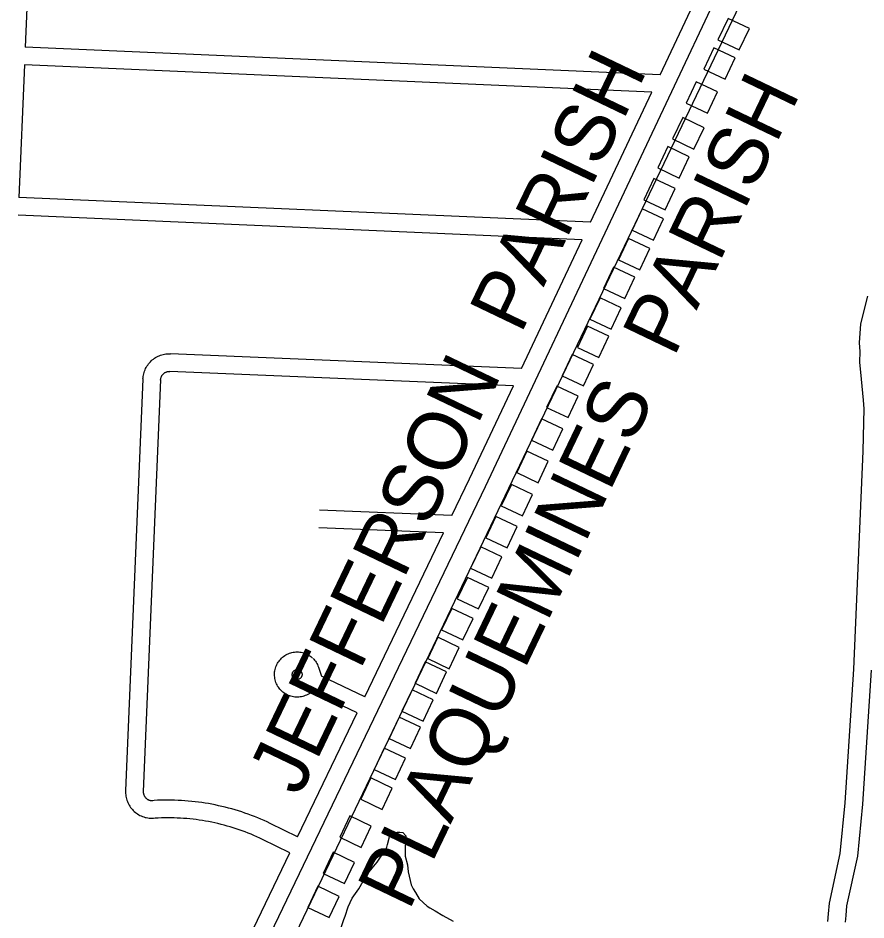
# Model space of a CAD drawing. Extents: x 3683402 to 3721514, y 487807 to 513565.
# Drawn here: x 3699136 to 3700574, y 507452 to 508980 of the extents above; entities that cross this region are included whole.
import ezdxf

# ---------------------------------------------------------------- set-up
doc = ezdxf.new("R2010")
doc.units = 0
for name, color, linetype in [('V-BLDG-OTLN', 7, 'Continuous'), ('V-ROAD-CNTR', 7, 'Continuous'), ('V-SITE-VEGE', 7, 'Continuous'), ('V-TOPO-BNDY', 7, 'Continuous'), ('V-TOPO-GNAM-IDEN', 7, 'Continuous')]:
    doc.layers.add(name, color=color, linetype=linetype)

msp = doc.modelspace()

# ---------------------------------------------------------------- linework, layer by layer
at = {"layer": 'V-BLDG-OTLN'}
for points in [[(3700339.8, 508979.8), (3700322.7, 508943.7), (3700358.8, 508926.6), (3700375.9, 508962.7)], [(3700315.7, 508929.9), (3700298.6, 508893.8), (3700334.8, 508876.7), (3700351.9, 508912.8)], [(3700285.6, 508872.4), (3700268.5, 508836.2), (3700304.7, 508819.1), (3700321.8, 508855.3)], [(3700262.9, 508811.5), (3700245.8, 508775.4), (3700282, 508758.3), (3700299.1, 508794.5)], [(3700237.9, 508762.4), (3700220.8, 508726.2), (3700257, 508709.1), (3700274.1, 508745.3)], [(3700214, 508708.3), (3700196.9, 508672.1), (3700233.1, 508655), (3700250.2, 508691.2)], [(3700194.1, 508657), (3700177, 508620.9), (3700213.2, 508603.8), (3700230.3, 508639.9)], [(3700171, 508606.6), (3700153.9, 508570.5), (3700190.1, 508553.4), (3700207.1, 508589.6)], [(3700145.8, 508558.3), (3700128.7, 508522.1), (3700164.9, 508505), (3700182, 508541.2)], [(3700122.7, 508506.2), (3700105.6, 508470), (3700141.7, 508452.9), (3700158.8, 508489.1)], [(3700101.5, 508458.2), (3700084.4, 508422), (3700120.5, 508404.9), (3700137.6, 508441.1)], [(3700075.5, 508410), (3700058.4, 508373.8), (3700094.6, 508356.7), (3700111.7, 508392.9)], [(3700049.3, 508356.3), (3700032.2, 508320.1), (3700068.4, 508303), (3700085.5, 508339.2)], [(3700023.7, 508301.2), (3700006.6, 508265.1), (3700042.8, 508248), (3700059.9, 508284.1)], [(3699998.8, 508246.1), (3699981.7, 508209.9), (3700017.8, 508192.8), (3700034.9, 508229)], [(3699972.3, 508189.7), (3699955.2, 508153.6), (3699991.3, 508136.5), (3700008.4, 508172.7)], [(3699945.9, 508135.7), (3699928.8, 508099.5), (3699965, 508082.4), (3699982.1, 508118.6)], [(3699920.3, 508084.3), (3699903.2, 508048.1), (3699939.3, 508031), (3699956.4, 508067.2)], [(3699897.7, 508032.2), (3699880.6, 507996), (3699916.8, 507978.9), (3699933.9, 508015.1)], [(3699871.2, 507979.6), (3699854.1, 507943.5), (3699890.3, 507926.4), (3699907.4, 507962.5)], [(3699847.6, 507930.7), (3699830.6, 507894.5), (3699866.7, 507877.4), (3699883.8, 507913.6)], [(3699826.4, 507889), (3699809.3, 507852.8), (3699845.5, 507835.7), (3699862.6, 507871.9)], [(3699803.9, 507841.8), (3699786.8, 507805.6), (3699822.9, 507788.5), (3699840, 507824.7)], [(3699782.3, 507795.3), (3699765.2, 507759.2), (3699801.4, 507742.1), (3699818.5, 507778.2)], [(3699756.7, 507742.7), (3699739.6, 507706.5), (3699775.8, 507689.4), (3699792.9, 507725.6)], [(3699734.2, 507692.3), (3699717.1, 507656.1), (3699753.2, 507639), (3699770.3, 507675.2)], [(3699698.5, 507627.8), (3699681.4, 507591.7), (3699717.6, 507574.6), (3699734.7, 507610.7)], [(3699670.4, 507566.3), (3699653.3, 507530.2), (3699689.5, 507513.1), (3699706.6, 507549.2)], [(3699644.3, 507508.7), (3699627.2, 507472.6), (3699663.3, 507455.5), (3699680.4, 507491.6)]]:
    msp.add_lwpolyline(points, close=True, dxfattribs=at)
at = {"layer": 'V-ROAD-CNTR'}
for points in [[(3699500.7, 507296.2), (3699928.4, 508186.2), (3700399.8, 509185.7), (3700409.1, 509207.3), (3700415, 509225.2), (3700418, 509244.9), (3700421.8, 509363)], [(3699157.5, 509155.7), (3699147.9, 508931.1)], [(3700224.4, 508884.1), (3700328.1, 509103.9)], [(3700224.4, 508884.1), (3699147.9, 508931.1)], [(3699146.6, 508901.1), (3699137, 508676.3)], [(3700210.5, 508854.7), (3699146.6, 508901.1)], [(3700106.5, 508634.1), (3700210.5, 508854.7)], [(3700106.5, 508634.1), (3699137, 508676.3)], [(3700092.6, 508604.7), (3699135.7, 508646.4)], [(3699989.5, 508386.1), (3700092.6, 508604.7)], [(3700509.2, 507449.2), (3700510.1, 507461.7), (3700511.6, 507480.1), (3700530.1, 507564.2), (3700538.5, 507650.3), (3700553.1, 507876.6), (3700568.8, 508246.1), (3700570.2, 508294.9), (3700570.5, 508318), (3700569.4, 508332.6), (3700566.1, 508368.3), (3700563.5, 508397.1), (3700563.7, 508415.2), (3700562.8, 508429.8), (3700565, 508461.9), (3700577, 508509)], [(3699347.6, 508368.7), (3699347.7, 508370.7), (3699348, 508373), (3699348.4, 508375.3), (3699348.9, 508377.5), (3699349.5, 508379.8), (3699350.3, 508382), (3699351.1, 508384.1), (3699352.1, 508386.2), (3699353.2, 508388.3), (3699354.3, 508390.3), (3699355.6, 508392.2), (3699357, 508394.1), (3699358.5, 508395.9), (3699360.1, 508397.6), (3699361.7, 508399.3), (3699363.4, 508400.8), (3699365.3, 508402.3), (3699367.1, 508403.6), (3699369.1, 508404.9), (3699371.1, 508406), (3699373.2, 508407.1), (3699375.3, 508408), (3699377.5, 508408.9), (3699379.7, 508409.6), (3699381.9, 508410.2), (3699384.2, 508410.7), (3699386.5, 508411), (3699388.8, 508411.3), (3699391.1, 508411.4), (3699393.3, 508411.4), (3699394.3, 508411.4)], [(3699989.5, 508386.1), (3699394.4, 508411.4)], [(3699377.5, 508366.7), (3699377.6, 508367.9), (3699377.7, 508368.6), (3699377.8, 508369.4), (3699378, 508370.1), (3699378.2, 508370.9), (3699378.4, 508371.6), (3699378.7, 508372.3), (3699379, 508373), (3699379.4, 508373.7), (3699379.8, 508374.4), (3699380.2, 508375), (3699380.7, 508375.7), (3699381.2, 508376.3), (3699381.7, 508376.8), (3699382.2, 508377.4), (3699382.8, 508377.9), (3699383.4, 508378.4), (3699384.1, 508378.8), (3699384.7, 508379.3), (3699385.4, 508379.6), (3699386.1, 508380), (3699386.8, 508380.3), (3699387.5, 508380.6), (3699388.2, 508380.8), (3699389, 508381), (3699389.7, 508381.2), (3699390.5, 508381.3), (3699391.3, 508381.4), (3699392, 508381.4), (3699392.9, 508381.4), (3699393.3, 508381.4)], [(3699975.7, 508356.7), (3699393.2, 508381.4)], [(3699347.6, 508368.3), (3699318.1, 507670.8)], [(3699377.5, 508367.1), (3699348.1, 507669.5)], [(3699871.6, 508137.2), (3699901.3, 508199.1), (3699975.7, 508356.7)], [(3699871.6, 508137.2), (3699646.8, 508146.2)], [(3699857.4, 508107.8), (3699645.6, 508116.2)], [(3699723.7, 507829.6), (3699857.4, 508107.8)], [(3699636.1, 507838.1), (3699624.8, 507832.6), (3699622.8, 507831.8), (3699620.6, 507831), (3699618.5, 507830.4), (3699616.3, 507829.9), (3699614.1, 507829.6), (3699611.8, 507829.3), (3699609.6, 507829.2), (3699607.4, 507829.3), (3699605.1, 507829.4), (3699602.9, 507829.7), (3699600.7, 507830.1), (3699598.5, 507830.7), (3699596.4, 507831.4), (3699594.3, 507832.2), (3699592.2, 507833.1), (3699590.2, 507834.1), (3699588.3, 507835.3), (3699586.5, 507836.6), (3699584.7, 507837.9), (3699583, 507839.4), (3699581.4, 507841), (3699579.9, 507842.7), (3699578.5, 507844.4), (3699577.2, 507846.2), (3699576, 507848.1), (3699574.9, 507850.1), (3699573.9, 507852.1), (3699573.1, 507854.2), (3699572.4, 507856.3), (3699571.8, 507858.5), (3699571.3, 507860.7), (3699571, 507862.9), (3699570.8, 507865.2), (3699570.7, 507867.4), (3699570.8, 507869.6), (3699570.9, 507871.9), (3699571.3, 507874.1), (3699571.7, 507876.3), (3699572.3, 507878.5), (3699573, 507880.6), (3699573.8, 507882.7), (3699574.7, 507884.7), (3699575.8, 507886.7), (3699577, 507888.6), (3699578.3, 507890.5), (3699579.7, 507892.2), (3699581.2, 507893.9), (3699582.7, 507895.5), (3699584.4, 507897), (3699586.2, 507898.4), (3699588, 507899.6), (3699589.9, 507900.8), (3699591.9, 507901.9), (3699594, 507902.8), (3699596, 507903.7), (3699598.2, 507904.3), (3699600.3, 507904.9), (3699602.5, 507905.4), (3699604.8, 507905.7), (3699607, 507905.9), (3699609.3, 507905.9), (3699611.5, 507905.8), (3699613.7, 507905.6), (3699616, 507905.3), (3699618.1, 507904.8), (3699620.3, 507904.2), (3699622.4, 507903.5), (3699624.5, 507902.7), (3699626.5, 507901.7), (3699628.5, 507900.6), (3699630.4, 507899.4), (3699632.2, 507898.1), (3699634, 507896.7), (3699635.3, 507895.5)], [(3699636, 507894.9), (3699637.2, 507893.6), (3699638.7, 507891.9), (3699640.1, 507890.1), (3699641.3, 507888.3), (3699642.5, 507886.3), (3699643.5, 507884.4), (3699644.4, 507882.3), (3699645.3, 507880.2), (3699650.2, 507864.6)], [(3699616.8, 507864.4), (3699616.4, 507863.6), (3699616.1, 507863.1), (3699615.8, 507862.7), (3699615.5, 507862.3), (3699615.2, 507862), (3699614.9, 507861.6), (3699614.5, 507861.3), (3699614.1, 507861), (3699613.8, 507860.7), (3699613.3, 507860.4), (3699612.9, 507860.2), (3699612.5, 507860), (3699612, 507859.8), (3699611.6, 507859.6), (3699611.1, 507859.5), (3699610.6, 507859.4), (3699610.1, 507859.3), (3699609.7, 507859.3), (3699609.2, 507859.2), (3699608.7, 507859.2), (3699608.2, 507859.3), (3699607.7, 507859.3), (3699607.2, 507859.4), (3699606.8, 507859.6), (3699606.3, 507859.7), (3699605.8, 507859.9), (3699605.4, 507860.1), (3699605, 507860.3), (3699604.5, 507860.6), (3699604.1, 507860.8), (3699603.7, 507861.1), (3699603.4, 507861.5), (3699603, 507861.8), (3699602.7, 507862.2), (3699602.4, 507862.5), (3699602.1, 507862.9), (3699601.9, 507863.3), (3699601.6, 507863.8), (3699601.4, 507864.2), (3699601.2, 507864.7), (3699601.1, 507865.1), (3699600.9, 507865.6), (3699600.8, 507866.1), (3699600.8, 507866.6), (3699600.7, 507867), (3699600.7, 507867.5), (3699600.7, 507868), (3699600.8, 507868.5), (3699600.8, 507869), (3699600.9, 507869.5), (3699601.1, 507869.9), (3699601.2, 507870.4), (3699601.4, 507870.9), (3699601.6, 507871.3), (3699601.8, 507871.7), (3699602.1, 507872.1), (3699602.4, 507872.5), (3699602.7, 507872.9), (3699603, 507873.3), (3699603.3, 507873.6), (3699603.7, 507874), (3699604.1, 507874.3), (3699604.5, 507874.5), (3699604.9, 507874.8), (3699605.3, 507875), (3699605.8, 507875.2), (3699606.2, 507875.4), (3699606.7, 507875.6), (3699607.2, 507875.7), (3699607.6, 507875.8), (3699608.1, 507875.9), (3699608.6, 507875.9), (3699609.1, 507875.9), (3699609.6, 507875.9), (3699610.1, 507875.8), (3699610.5, 507875.8), (3699611, 507875.7), (3699611.5, 507875.5), (3699612, 507875.4), (3699612.4, 507875.2), (3699612.8, 507875), (3699613.3, 507874.8), (3699613.7, 507874.5), (3699614.1, 507874.2), (3699614.5, 507873.9), (3699615.1, 507873.3)], [(3699614.5, 507873.9), (3699615.2, 507873.2), (3699615.5, 507872.9), (3699615.8, 507872.5), (3699616.1, 507872.1), (3699616.3, 507871.7), (3699616.5, 507871.2), (3699616.7, 507870.8), (3699616.9, 507870.3), (3699617.1, 507869.9), (3699617.2, 507869.4), (3699617.3, 507868.9), (3699617.3, 507868.4), (3699617.4, 507867.9), (3699617.4, 507867.4), (3699617.4, 507867), (3699617.3, 507866.5), (3699617.2, 507866), (3699617.1, 507865.5), (3699617, 507865), (3699616.8, 507864.6), (3699616.6, 507864), (3699616.5, 507863.8)], [(3700539.2, 507447.6), (3700540, 507459.4), (3700541.4, 507475.7), (3700559.8, 507559.5), (3700568.4, 507647.9), (3700583, 507875)], [(3699723.7, 507829.6), (3699650.2, 507864.6)], [(3699710.7, 507802.6), (3699636.1, 507838.1)], [(3699609.9, 507592.7), (3699710.7, 507802.6)], [(3699318.1, 507670.4), (3699318.1, 507668.5), (3699318.2, 507666.1), (3699318.4, 507663.8), (3699318.7, 507661.5), (3699319.1, 507659.2), (3699319.7, 507657), (3699320.4, 507654.8), (3699321.1, 507652.6), (3699322, 507650.4), (3699323, 507648.3), (3699324.2, 507646.3), (3699325.4, 507644.3), (3699326.7, 507642.4), (3699328.1, 507640.6), (3699329.6, 507638.8), (3699331.2, 507637.1), (3699332.9, 507635.5), (3699334.7, 507634), (3699336.5, 507632.6), (3699338.4, 507631.3), (3699340.4, 507630), (3699342.4, 507628.9), (3699344.5, 507627.9), (3699346.7, 507627), (3699348.8, 507626.2), (3699351.1, 507625.5), (3699353.3, 507625), (3699355.6, 507624.5), (3699357.9, 507624.2), (3699360.2, 507624), (3699362.5, 507623.9), (3699364.8, 507623.9), (3699365.7, 507624)], [(3699348.1, 507669.9), (3699348.1, 507668.8), (3699348.1, 507668), (3699348.2, 507667.2), (3699348.3, 507666.4), (3699348.4, 507665.7), (3699348.6, 507664.9), (3699348.8, 507664.2), (3699349.1, 507663.5), (3699349.4, 507662.7), (3699349.7, 507662.1), (3699350.1, 507661.4), (3699350.5, 507660.7), (3699351, 507660.1), (3699351.4, 507659.5), (3699351.9, 507658.9), (3699352.5, 507658.3), (3699353, 507657.8), (3699353.6, 507657.3), (3699354.2, 507656.8), (3699354.9, 507656.4), (3699355.5, 507655.9), (3699356.2, 507655.6), (3699356.9, 507655.2), (3699357.6, 507654.9), (3699358.3, 507654.7), (3699359.1, 507654.4), (3699359.8, 507654.3), (3699360.6, 507654.1), (3699361.4, 507654), (3699362.1, 507653.9), (3699362.9, 507653.9), (3699363.8, 507653.9), (3699364.2, 507653.9)], [(3699609.9, 507592.7), (3699563.4, 507615.3), (3699558.2, 507617.7), (3699552.9, 507620.1), (3699547.6, 507622.4), (3699542.2, 507624.7), (3699536.9, 507626.8), (3699531.5, 507628.9), (3699526, 507630.9), (3699520.5, 507632.8), (3699515.1, 507634.7), (3699509.5, 507636.4), (3699504, 507638.1), (3699498.4, 507639.7), (3699492.8, 507641.2), (3699487.2, 507642.7), (3699481.6, 507644), (3699475.9, 507645.3), (3699470.3, 507646.5), (3699464.6, 507647.6), (3699458.9, 507648.7), (3699453.2, 507649.6), (3699447.5, 507650.5), (3699441.7, 507651.3), (3699436, 507652), (3699430.2, 507652.6), (3699424.4, 507653.2), (3699418.7, 507653.7), (3699412.9, 507654), (3699407.1, 507654.3), (3699401.3, 507654.5), (3699395.5, 507654.7), (3699389.7, 507654.7), (3699383.9, 507654.7), (3699378.1, 507654.6), (3699372.4, 507654.4), (3699366.6, 507654.1), (3699360.6, 507653.7), (3699360.3, 507653.7)], [(3699596.9, 507565.6), (3699550.5, 507588.2), (3699545.6, 507590.5), (3699540.7, 507592.7), (3699535.8, 507594.8), (3699530.9, 507596.9), (3699525.9, 507598.9), (3699520.9, 507600.8), (3699515.9, 507602.7), (3699510.8, 507604.4), (3699505.7, 507606.1), (3699500.6, 507607.8), (3699495.5, 507609.3), (3699490.3, 507610.8), (3699485.2, 507612.2), (3699480, 507613.6), (3699474.7, 507614.8), (3699469.5, 507616), (3699464.3, 507617.1), (3699459, 507618.2), (3699453.7, 507619.1), (3699448.4, 507620), (3699443.1, 507620.8), (3699437.8, 507621.6), (3699432.5, 507622.2), (3699427.2, 507622.8), (3699421.8, 507623.3), (3699416.5, 507623.7), (3699411.1, 507624.1), (3699405.8, 507624.4), (3699400.4, 507624.6), (3699395.1, 507624.7), (3699389.7, 507624.7), (3699384.3, 507624.7), (3699379, 507624.6), (3699373.6, 507624.4), (3699368.3, 507624.1), (3699363.1, 507623.8), (3699363.4, 507623.8)], [(3699473.5, 507308.9), (3699596.9, 507565.6)]]:
    msp.add_lwpolyline(points, dxfattribs=at)
at = {"layer": 'V-SITE-VEGE'}
for points in [[(3699765.1, 507590), (3699766.2, 507595.2), (3699769.7, 507598), (3699775.5, 507599.2), (3699779, 507600.3), (3699783, 507600.3), (3699788.2, 507599.7), (3699793.4, 507593.9), (3699793.4, 507591), (3699793.9, 507589.9)], [(3699682.6, 507435.4), (3699688.4, 507452.2), (3699690.7, 507457.9), (3699695.4, 507474.1), (3699702.4, 507488.5), (3699708.2, 507496.6), (3699713.4, 507504.1), (3699721, 507517.3), (3699731.4, 507532.9), (3699736, 507539.2), (3699744.7, 507549.6), (3699758.7, 507570.3), (3699761, 507575), (3699762.1, 507579.6), (3699765.1, 507590)], [(3699793.9, 507589.9), (3699793.9, 507585.3), (3699794.5, 507582.4), (3699794.1, 507579.1), (3699793.4, 507578.8), (3699792.2, 507578.3), (3699792.1, 507559.8), (3699796.1, 507544.8), (3699797.2, 507533.3), (3699802.4, 507511.3), (3699805.8, 507504.4), (3699809.8, 507498), (3699816.2, 507487.6), (3699829.4, 507474.8), (3699834, 507471.9), (3699843.2, 507467.3), (3699855.9, 507459.2), (3699873.8, 507449.3)]]:
    msp.add_lwpolyline(points, dxfattribs=at)
at = {"layer": 'V-TOPO-BNDY'}
for p, q in [((3700766.6, 509854.3), (3699832.7, 507901.8)), ((3699832.7, 507901.8), (3697207.3, 502413.5))]:
    msp.add_line(p, q, dxfattribs=at)

# ---------------------------------------------------------------- texts
at = {"layer": 'V-TOPO-GNAM-IDEN'}
for s, p in [('JEFFERSON  PARISH', (3699612.9, 507659)), ('PLAQUEMINES  PARISH', (3699798.5, 507465.3))]:
    msp.add_text(s, height=100, rotation=64.4113, dxfattribs=at).set_placement(p)

doc.saveas('drawing.dxf')
